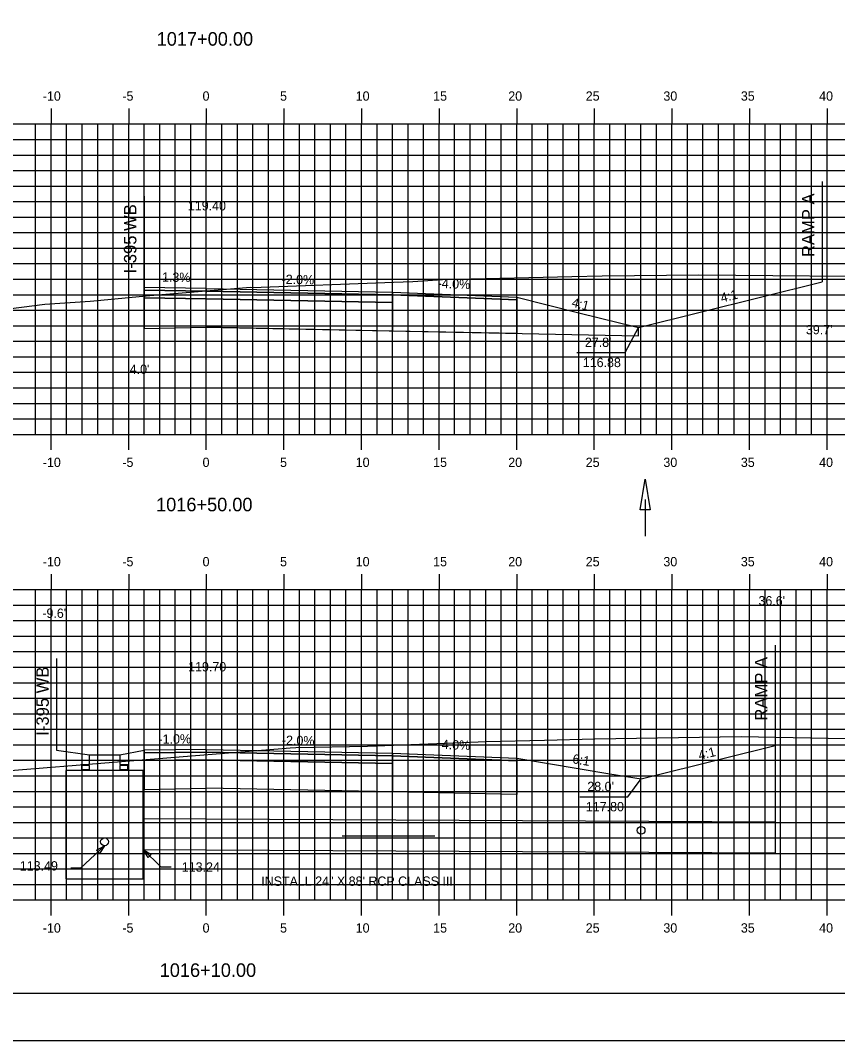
# Model space of a CAD drawing. Extents: x 853291 to 853462, y 365624 to 365734.
# Drawn here: x 853361.8 to 853414.5, y 365624 to 365689.7 of the extents above; entities that cross this region are included whole.
import ezdxf

# ---------------------------------------------------------------- set-up
doc = ezdxf.new("R2010")
doc.units = 0
for name, color, linetype in [('ANNOTATION', 7, 'Continuous'), ('BORDER', 7, 'Continuous'), ('D_Drainage_CB_TypeA1-B1', 7, 'Continuous'), ('D_Drainage_Culvert', 7, 'Continuous'), ('D_Drainage_Ditch_Line', 7, 'Continuous'), ('D_Drainage_Text', 7, 'Continuous'), ('D_Roadway_Centerline', 7, 'Continuous'), ('D_Roadway_Centerline_Text', 7, 'Continuous'), ('D_Roadway_Edge_Shoulder', 7, 'Continuous'), ('D_Roadway_Edge_TW', 7, 'Continuous'), ('D_Roadway_FinishedGrade', 7, 'Continuous'), ('D_Roadway_Pavement', 7, 'Continuous'), ('D_Roadway_SubGrade', 7, 'Continuous'), ('D_Text_Standard', 7, 'Continuous'), ('Default', 7, 'Continuous'), ('H_V ANNOTATION', 7, 'Continuous'), ('M_Roadway_Centerline', 7, 'Continuous'), ('MAJOR', 7, 'Continuous'), ('MINOR', 7, 'Continuous'), ('PLOT BOUNDARY', 7, 'Continuous'), ('S_Roadway_Centerline', 7, 'Continuous')]:
    doc.layers.add(name, color=color, linetype=linetype)

msp = doc.modelspace()

# ---------------------------------------------------------------- linework, layer by layer
at = {"layer": 'ANNOTATION'}
msp.add_line((853410.467, 365642.983), (853410.467, 365636.07), dxfattribs=at)
for points in [[(853397.691, 365668.298), (853400.801, 365668.298), (853401.666, 365669.903)], [(853397.875, 365639.678), (853400.985, 365639.678), (853401.839, 365640.83)]]:
    msp.add_lwpolyline(points, dxfattribs=at)
at = {"layer": 'BORDER'}
msp.add_lwpolyline([(853298.818, 365627.027), (853458.818, 365627.027), (853458.818, 365732.027), (853298.818, 365732.027)], close=True, dxfattribs=at)
at = {"layer": 'D_Drainage_CB_TypeA1-B1'}
msp.add_lwpolyline([(853365.758, 365641.753), (853366.283, 365641.753), (853366.283, 365642.377), (853368.252, 365642.377), (853368.252, 365641.753), (853368.777, 365641.753)], dxfattribs=at)
for points in [[(853364.774, 365634.386), (853369.757, 365634.386), (853369.757, 365641.372), (853364.774, 365641.372)], [(853365.783, 365641.69), (853365.783, 365641.44), (853366.283, 365641.44), (853366.283, 365641.69)], [(853368.252, 365641.69), (853368.252, 365641.44), (853368.752, 365641.44), (853368.752, 365641.69)]]:
    msp.add_lwpolyline(points, close=True, dxfattribs=at)
at = {"layer": 'D_Drainage_Culvert'}
for p, q in [((853369.757, 365638.273), (853410.467, 365638.07)), ((853382.565, 365637.171), (853388.534, 365637.171)), ((853369.757, 365636.273), (853410.467, 365636.07))]:
    msp.add_line(p, q, dxfattribs=at)
for centre in [(853401.832, 365637.514), (853367.261, 365636.776)]:
    msp.add_circle(centre, 0.25, dxfattribs=at)
at = {"layer": 'D_Drainage_Ditch_Line'}
msp.add_line((853402.091, 365658.824), (853402.091, 365656.474), dxfattribs=at)
msp.add_lwpolyline([(853402.419, 365658.167), (853401.763, 365658.167), (853402.091, 365660.136)], close=True, dxfattribs=at)
at = {"layer": 'D_Roadway_Centerline'}
for p, q in [((853364.175, 365642.691), (853366.283, 365642.377)), ((853368.252, 365642.377), (853369.817, 365642.682)), ((853410.467, 365642.983), (853410.467, 365640.483))]:
    msp.add_line(p, q, dxfattribs=at)
for points in [[(853401.666, 365669.903), (853405.544, 365670.869), (853413.506, 365672.851)], [(853393.818, 365671.865), (853397.818, 365670.865), (853401.666, 365669.903)], [(853401.839, 365640.83), (853407.088, 365642.14), (853410.467, 365642.983)], [(853393.822, 365642.166), (853399.822, 365641.166), (853401.839, 365640.83)]]:
    msp.add_lwpolyline(points, dxfattribs=at)
at = {"layer": 'D_Roadway_Edge_Shoulder'}
for points in [[(853373.818, 365672.425), (853369.818, 365672.481), (853369.818, 365672.314), (853373.818, 365672.258)], [(853385.818, 365672.185), (853393.818, 365671.865), (853393.818, 365671.698), (853385.818, 365672.018)], [(853373.818, 365642.723), (853369.817, 365642.682), (853369.817, 365642.516), (853373.818, 365642.557)], [(853385.821, 365642.485), (853393.822, 365642.166), (853393.822, 365642), (853385.821, 365642.319)]]:
    msp.add_lwpolyline(points, close=True, dxfattribs=at)
at = {"layer": 'D_Roadway_Edge_TW'}
for points in [[(853373.818, 365672.425), (853385.818, 365672.185), (853385.818, 365672.018), (853373.818, 365672.258)], [(853373.818, 365642.723), (853385.821, 365642.485), (853385.821, 365642.319), (853373.818, 365642.557)]]:
    msp.add_lwpolyline(points, close=True, dxfattribs=at)
for points in [[(853385.818, 365672.185), (853385.818, 365672.018)], [(853385.821, 365642.485), (853385.821, 365642.319)]]:
    msp.add_lwpolyline(points, dxfattribs=at)
at = {"layer": 'D_Roadway_FinishedGrade'}
for p, q in [((853369.818, 365672.481), (853369.818, 365672.231)), ((853373.818, 365672.425), (853373.818, 365672.175)), ((853385.818, 365672.185), (853385.818, 365671.935)), ((853393.818, 365671.865), (853393.818, 365671.615)), ((853369.817, 365642.682), (853369.817, 365642.432)), ((853373.818, 365642.723), (853373.818, 365642.473)), ((853385.821, 365642.485), (853385.821, 365642.235)), ((853393.822, 365642.166), (853393.822, 365641.916))]:
    msp.add_line(p, q, dxfattribs=at)
at = {"layer": 'D_Roadway_Pavement'}
for points in [[(853373.818, 365672.258), (853369.818, 365672.314), (853369.818, 365671.814), (853373.818, 365671.758)], [(853373.818, 365672.258), (853385.818, 365672.018), (853385.818, 365671.518), (853373.818, 365671.758)], [(853373.818, 365642.557), (853369.817, 365642.516), (853369.817, 365642.016), (853373.818, 365642.057)], [(853373.818, 365642.557), (853385.821, 365642.319), (853385.821, 365641.819), (853373.818, 365642.057)]]:
    msp.add_lwpolyline(points, close=True, dxfattribs=at)
for points in [[(853385.818, 365672.018), (853385.818, 365671.518)], [(853385.818, 365672.018), (853385.818, 365671.518)], [(853385.821, 365642.319), (853385.821, 365641.819)], [(853385.821, 365642.319), (853385.821, 365641.819)]]:
    msp.add_lwpolyline(points, dxfattribs=at)
at = {"layer": 'D_Roadway_SubGrade'}
for p, q in [((853413.506, 365679.312), (853413.506, 365672.851)), ((853369.818, 365678.385), (853369.818, 365669.845)), ((853410.467, 365649.445), (853410.467, 365636.07)), ((853364.175, 365648.595), (853364.175, 365642.691))]:
    msp.add_line(p, q, dxfattribs=at)
for points in [[(853373.818, 365671.758), (853369.818, 365671.814), (853369.818, 365672.314), (853369.818, 365672.481), (853369.818, 365669.845), (853373.818, 365669.925)], [(853373.818, 365671.758), (853385.818, 365671.518), (853385.818, 365669.685), (853373.818, 365669.925)], [(853385.818, 365671.518), (853385.818, 365672.018), (853393.818, 365671.698), (853393.818, 365671.865), (853393.818, 365669.525), (853385.818, 365669.685)], [(853373.818, 365642.057), (853369.817, 365642.016), (853369.817, 365642.516), (853369.817, 365642.682), (853369.817, 365640.142), (853373.818, 365640.223)], [(853373.818, 365642.057), (853385.821, 365641.819), (853385.821, 365639.985), (853373.818, 365640.223)], [(853385.821, 365641.819), (853385.821, 365642.319), (853393.822, 365642), (853393.822, 365642.166), (853393.822, 365639.826), (853385.821, 365639.985)]]:
    msp.add_lwpolyline(points, close=True, dxfattribs=at)
for points in [[(853385.818, 365671.518), (853385.818, 365669.685)], [(853373.818, 365669.925), (853401.655, 365669.368), (853401.666, 365669.903)], [(853385.821, 365641.819), (853385.821, 365639.985)]]:
    msp.add_lwpolyline(points, dxfattribs=at)
at = {"layer": 'D_Text_Standard'}
for points in [[(853367.261, 365636.526), (853365.715, 365635.084), (853365.095, 365635.084)], [(853369.757, 365636.273), (853370.879, 365635.153), (853371.559, 365635.153)]]:
    msp.add_lwpolyline(points, dxfattribs=at)
for points in [[(853367.261, 365636.526), (853366.94, 365636.019), (853366.739, 365636.23)], [(853369.757, 365636.273), (853370.272, 365635.965), (853370.066, 365635.759)]]:
    msp.add_lwpolyline(points, close=True, dxfattribs=at)
at = {"layer": 'Default'}
msp.add_lwpolyline([(853393.818, 365671.865), (853397.818, 365670.865), (853401.666, 365669.903)], dxfattribs=at)
at = {"layer": 'MAJOR'}
for p, q in [((853363.818, 365684.029), (853363.818, 365683.027)), ((853368.818, 365684.029), (853368.818, 365683.027)), ((853373.818, 365684.029), (853373.818, 365683.027)), ((853378.818, 365684.029), (853378.818, 365683.027)), ((853383.818, 365684.029), (853383.818, 365683.027)), ((853388.818, 365684.029), (853388.818, 365683.027)), ((853393.818, 365684.029), (853393.818, 365683.027)), ((853398.818, 365684.029), (853398.818, 365683.027)), ((853403.818, 365684.029), (853403.818, 365683.027)), ((853408.818, 365684.029), (853408.818, 365683.027)), ((853413.818, 365684.029), (853413.818, 365683.027)), ((853303.818, 365683.027), (853443.818, 365683.027)), ((853303.818, 365683.027), (853443.818, 365683.027)), ((853363.818, 365663.027), (853363.818, 365683.027)), ((853368.818, 365663.027), (853368.818, 365683.027)), ((853373.818, 365663.027), (853373.818, 365683.027)), ((853378.818, 365663.027), (853378.818, 365683.027)), ((853383.818, 365663.027), (853383.818, 365683.027)), ((853388.818, 365663.027), (853388.818, 365683.027)), ((853393.818, 365663.027), (853393.818, 365683.027)), ((853398.818, 365663.027), (853398.818, 365683.027)), ((853403.818, 365663.027), (853403.818, 365683.027)), ((853408.818, 365663.027), (853408.818, 365683.027)), ((853413.818, 365663.027), (853413.818, 365683.027)), ((853303.818, 365678.027), (853443.818, 365678.027)), ((853303.818, 365673.027), (853443.818, 365673.027)), ((853303.818, 365668.027), (853443.818, 365668.027)), ((853303.818, 365663.027), (853443.818, 365663.027)), ((853303.818, 365663.027), (853443.818, 365663.027)), ((853363.818, 365662.025), (853363.818, 365663.027)), ((853368.818, 365662.025), (853368.818, 365663.027)), ((853373.818, 365662.025), (853373.818, 365663.027)), ((853378.818, 365662.025), (853378.818, 365663.027)), ((853383.818, 365662.025), (853383.818, 365663.027)), ((853388.818, 365662.025), (853388.818, 365663.027)), ((853393.818, 365662.025), (853393.818, 365663.027)), ((853398.818, 365662.025), (853398.818, 365663.027)), ((853403.818, 365662.025), (853403.818, 365663.027)), ((853408.818, 365662.025), (853408.818, 365663.027)), ((853413.818, 365662.025), (853413.818, 365663.027)), ((853363.818, 365654.029), (853363.818, 365653.027)), ((853368.818, 365654.029), (853368.818, 365653.027)), ((853373.818, 365654.029), (853373.818, 365653.027)), ((853378.818, 365654.029), (853378.818, 365653.027)), ((853383.818, 365654.029), (853383.818, 365653.027)), ((853388.818, 365654.029), (853388.818, 365653.027)), ((853393.818, 365654.029), (853393.818, 365653.027)), ((853398.818, 365654.029), (853398.818, 365653.027)), ((853403.818, 365654.029), (853403.818, 365653.027)), ((853408.818, 365654.029), (853408.818, 365653.027)), ((853413.818, 365654.029), (853413.818, 365653.027)), ((853303.818, 365653.027), (853443.818, 365653.027)), ((853303.818, 365653.027), (853443.818, 365653.027)), ((853363.818, 365633.027), (853363.818, 365653.027)), ((853368.818, 365633.027), (853368.818, 365653.027)), ((853373.818, 365633.027), (853373.818, 365653.027)), ((853378.818, 365633.027), (853378.818, 365653.027)), ((853383.818, 365633.027), (853383.818, 365653.027)), ((853388.818, 365633.027), (853388.818, 365653.027)), ((853393.818, 365633.027), (853393.818, 365653.027)), ((853398.818, 365633.027), (853398.818, 365653.027)), ((853403.818, 365633.027), (853403.818, 365653.027)), ((853408.818, 365633.027), (853408.818, 365653.027)), ((853413.818, 365633.027), (853413.818, 365653.027)), ((853303.818, 365648.027), (853443.818, 365648.027)), ((853303.818, 365643.027), (853443.818, 365643.027)), ((853303.818, 365638.027), (853443.818, 365638.027)), ((853303.818, 365633.027), (853443.818, 365633.027)), ((853303.818, 365633.027), (853443.818, 365633.027)), ((853363.818, 365632.025), (853363.818, 365633.027)), ((853368.818, 365632.025), (853368.818, 365633.027)), ((853373.818, 365632.025), (853373.818, 365633.027)), ((853378.818, 365632.025), (853378.818, 365633.027)), ((853383.818, 365632.025), (853383.818, 365633.027)), ((853388.818, 365632.025), (853388.818, 365633.027)), ((853393.818, 365632.025), (853393.818, 365633.027)), ((853398.818, 365632.025), (853398.818, 365633.027)), ((853403.818, 365632.025), (853403.818, 365633.027)), ((853408.818, 365632.025), (853408.818, 365633.027)), ((853413.818, 365632.025), (853413.818, 365633.027))]:
    msp.add_line(p, q, dxfattribs=at)
at = {"layer": 'MINOR'}
for p, q in [((853362.818, 365663.027), (853362.818, 365683.027)), ((853364.818, 365663.027), (853364.818, 365683.027)), ((853365.818, 365663.027), (853365.818, 365683.027)), ((853366.818, 365663.027), (853366.818, 365683.027)), ((853367.818, 365663.027), (853367.818, 365683.027)), ((853369.818, 365663.027), (853369.818, 365683.027)), ((853370.818, 365663.027), (853370.818, 365683.027)), ((853371.818, 365663.027), (853371.818, 365683.027)), ((853372.818, 365663.027), (853372.818, 365683.027)), ((853374.818, 365663.027), (853374.818, 365683.027)), ((853375.818, 365663.027), (853375.818, 365683.027)), ((853376.818, 365663.027), (853376.818, 365683.027)), ((853377.818, 365663.027), (853377.818, 365683.027)), ((853379.818, 365663.027), (853379.818, 365683.027)), ((853380.818, 365663.027), (853380.818, 365683.027)), ((853381.818, 365663.027), (853381.818, 365683.027)), ((853382.818, 365663.027), (853382.818, 365683.027)), ((853384.818, 365663.027), (853384.818, 365683.027)), ((853385.818, 365663.027), (853385.818, 365683.027)), ((853386.818, 365663.027), (853386.818, 365683.027)), ((853387.818, 365663.027), (853387.818, 365683.027)), ((853389.818, 365663.027), (853389.818, 365683.027)), ((853390.818, 365663.027), (853390.818, 365683.027)), ((853391.818, 365663.027), (853391.818, 365683.027)), ((853392.818, 365663.027), (853392.818, 365683.027)), ((853394.818, 365663.027), (853394.818, 365683.027)), ((853395.818, 365663.027), (853395.818, 365683.027)), ((853396.818, 365663.027), (853396.818, 365683.027)), ((853397.818, 365663.027), (853397.818, 365683.027)), ((853399.818, 365663.027), (853399.818, 365683.027)), ((853400.818, 365663.027), (853400.818, 365683.027)), ((853401.818, 365663.027), (853401.818, 365683.027)), ((853402.818, 365663.027), (853402.818, 365683.027)), ((853404.818, 365663.027), (853404.818, 365683.027)), ((853405.818, 365663.027), (853405.818, 365683.027)), ((853406.818, 365663.027), (853406.818, 365683.027)), ((853407.818, 365663.027), (853407.818, 365683.027)), ((853409.818, 365663.027), (853409.818, 365683.027)), ((853410.818, 365663.027), (853410.818, 365683.027)), ((853411.818, 365663.027), (853411.818, 365683.027)), ((853412.818, 365663.027), (853412.818, 365683.027)), ((853303.818, 365682.027), (853443.818, 365682.027)), ((853303.818, 365681.027), (853443.818, 365681.027)), ((853303.818, 365680.027), (853443.818, 365680.027)), ((853303.818, 365679.027), (853443.818, 365679.027)), ((853303.818, 365677.027), (853443.818, 365677.027)), ((853303.818, 365676.027), (853443.818, 365676.027)), ((853303.818, 365675.027), (853443.818, 365675.027)), ((853303.818, 365674.027), (853443.818, 365674.027)), ((853303.818, 365672.027), (853443.818, 365672.027)), ((853303.818, 365671.027), (853443.818, 365671.027)), ((853303.818, 365670.027), (853443.818, 365670.027)), ((853303.818, 365669.027), (853443.818, 365669.027)), ((853303.818, 365667.027), (853443.818, 365667.027)), ((853303.818, 365666.027), (853443.818, 365666.027)), ((853303.818, 365665.027), (853443.818, 365665.027)), ((853303.818, 365664.027), (853443.818, 365664.027)), ((853362.818, 365633.027), (853362.818, 365653.027)), ((853364.818, 365633.027), (853364.818, 365653.027)), ((853365.818, 365633.027), (853365.818, 365653.027)), ((853366.818, 365633.027), (853366.818, 365653.027)), ((853367.818, 365633.027), (853367.818, 365653.027)), ((853369.818, 365633.027), (853369.818, 365653.027)), ((853370.818, 365633.027), (853370.818, 365653.027)), ((853371.818, 365633.027), (853371.818, 365653.027)), ((853372.818, 365633.027), (853372.818, 365653.027)), ((853374.818, 365633.027), (853374.818, 365653.027)), ((853375.818, 365633.027), (853375.818, 365653.027)), ((853376.818, 365633.027), (853376.818, 365653.027)), ((853377.818, 365633.027), (853377.818, 365653.027)), ((853379.818, 365633.027), (853379.818, 365653.027)), ((853380.818, 365633.027), (853380.818, 365653.027)), ((853381.818, 365633.027), (853381.818, 365653.027)), ((853382.818, 365633.027), (853382.818, 365653.027)), ((853384.818, 365633.027), (853384.818, 365653.027)), ((853385.818, 365633.027), (853385.818, 365653.027)), ((853386.818, 365633.027), (853386.818, 365653.027)), ((853387.818, 365633.027), (853387.818, 365653.027)), ((853389.818, 365633.027), (853389.818, 365653.027)), ((853390.818, 365633.027), (853390.818, 365653.027)), ((853391.818, 365633.027), (853391.818, 365653.027)), ((853392.818, 365633.027), (853392.818, 365653.027)), ((853394.818, 365633.027), (853394.818, 365653.027)), ((853395.818, 365633.027), (853395.818, 365653.027)), ((853396.818, 365633.027), (853396.818, 365653.027)), ((853397.818, 365633.027), (853397.818, 365653.027)), ((853399.818, 365633.027), (853399.818, 365653.027)), ((853400.818, 365633.027), (853400.818, 365653.027)), ((853401.818, 365633.027), (853401.818, 365653.027)), ((853402.818, 365633.027), (853402.818, 365653.027)), ((853404.818, 365633.027), (853404.818, 365653.027)), ((853405.818, 365633.027), (853405.818, 365653.027)), ((853406.818, 365633.027), (853406.818, 365653.027)), ((853407.818, 365633.027), (853407.818, 365653.027)), ((853409.818, 365633.027), (853409.818, 365653.027)), ((853410.818, 365633.027), (853410.818, 365653.027)), ((853411.818, 365633.027), (853411.818, 365653.027)), ((853412.818, 365633.027), (853412.818, 365653.027)), ((853303.818, 365652.027), (853443.818, 365652.027)), ((853303.818, 365651.027), (853443.818, 365651.027)), ((853303.818, 365650.027), (853443.818, 365650.027)), ((853303.818, 365649.027), (853443.818, 365649.027)), ((853303.818, 365647.027), (853443.818, 365647.027)), ((853303.818, 365646.027), (853443.818, 365646.027)), ((853303.818, 365645.027), (853443.818, 365645.027)), ((853303.818, 365644.027), (853443.818, 365644.027)), ((853303.818, 365642.027), (853443.818, 365642.027)), ((853303.818, 365641.027), (853443.818, 365641.027)), ((853303.818, 365640.027), (853443.818, 365640.027)), ((853303.818, 365639.027), (853443.818, 365639.027)), ((853303.818, 365637.027), (853443.818, 365637.027)), ((853303.818, 365636.027), (853443.818, 365636.027)), ((853303.818, 365635.027), (853443.818, 365635.027)), ((853303.818, 365634.027), (853443.818, 365634.027))]:
    msp.add_line(p, q, dxfattribs=at)
at = {"layer": 'PLOT BOUNDARY'}
msp.add_lwpolyline([(853290.725, 365623.968), (853460.725, 365623.968), (853460.725, 365733.968), (853290.725, 365733.968)], close=True, dxfattribs=at)
at = {"layer": 'S_Roadway_Centerline'}
for points in [[(853358.875, 365670.837), (853363.418, 365671.415), (853366.332, 365671.608), (853370.17, 365671.984), (853376.668, 365672.507), (853376.793, 365672.501), (853385.888, 365672.827), (853387.116, 365672.883), (853389.357, 365673.032), (853389.951, 365673.032), (853397.371, 365673.197), (853399.332, 365673.233), (853405.546, 365673.305), (853419.84, 365673.18), (853423.032, 365673.134), (853423.924, 365673.108), (853426.083, 365673.03), (853429.997, 365672.918), (853435.022, 365672.7), (853439.425, 365672.472), (853442.303, 365672.336), (853443.818, 365672.022)], [(853359.562, 365641.24), (853378.698, 365642.784), (853379.227, 365642.835), (853379.596, 365642.847), (853384.21, 365642.929), (853389.782, 365643.151), (853391.849, 365643.245), (853395.6, 365643.328), (853398.86, 365643.411), (853408.287, 365643.553), (853418.351, 365643.372), (853419.706, 365643.349), (853423.234, 365643.292), (853424.384, 365643.233), (853430.917, 365642.97), (853432.314, 365642.913), (853435.76, 365642.761), (853439.046, 365642.595), (853441.367, 365642.215), (853443.818, 365641.784)]]:
    msp.add_lwpolyline(points, dxfattribs=at)

# ---------------------------------------------------------------- texts
at = {"layer": 'ANNOTATION'}
for s, height, rotation, p in [('RAMP A', 0.8, 90, (853412.999, 365674.453)), ('I-395 WB', 0.8, 90, (853369.311, 365673.399)), ('1.3%', 0.6, 359.19792, (853370.961, 365672.865)), ('-2.0%', 0.6, 358.85423, (853378.663, 365672.728)), ('-4.0%', 0.6, 357.7093, (853388.715, 365672.47)), ('4:1', 0.6, 13.98162, (853407.032, 365671.514)), ('4:1', 0.6, 345.96376, (853397.317, 365671.265)), ("27.8' ", 0.6, 360, (853398.209, 365668.661)), ('116.88', 0.6, 360, (853398.075, 365667.361)), ('RAMP A', 0.8, 90, (853409.96, 365644.585)), ('I-395 WB', 0.8, 90, (853363.668, 365643.609)), ('-1.0%', 0.6, 0.579, (853370.74, 365643.092)), ('-2.0%', 0.6, 358.86451, (853378.684, 365643.027)), ('-4.0%', 0.6, 357.71985, (853388.717, 365642.77)), ('4:1', 0.6, 14.01143, (853405.599, 365642.043)), ('6:1', 0.6, 350.53768, (853397.377, 365641.844)), ("28.0' ", 0.6, 360, (853398.366, 365640.041)), ('117.80', 0.6, 360, (853398.272, 365638.741))]:
    msp.add_text(s, height=height, rotation=rotation, dxfattribs=at).set_placement(p)
at = {"layer": 'D_Drainage_Text'}
msp.add_text('INSTALL 24" X 88\' RCP CLASS III', height=0.6, dxfattribs=at).set_placement((853377.355, 365633.94))
at = {"layer": 'D_Roadway_Centerline'}
for s, p in [('C', (853373.813, 365672.425)), ('L', (853373.818, 365672.417))]:
    msp.add_text(s, height=0.0146, dxfattribs=at).set_placement(p)
at = {"layer": 'D_Roadway_Centerline_Text'}
for s, p in [('119.40', (853372.63, 365677.457)), ('119.70', (853372.646, 365647.755))]:
    msp.add_text(s, height=0.6, dxfattribs=at).set_placement(p)
at = {"layer": 'D_Text_Standard'}
for s, p in [("39.7'", (853412.449, 365669.476)), ("4.0'", (853368.884, 365666.926)), ("36.6'", (853409.394, 365652.009)), ("-9.6'", (853363.252, 365651.204)), ('113.49', (853361.801, 365634.927)), ('113.24', (853372.239, 365634.853))]:
    msp.add_text(s, height=0.6, dxfattribs=at).set_placement(p)
at = {"layer": 'H_V ANNOTATION'}
for s, height, p in [('1017+00.00', 0.875, (853370.619, 365688.07)), ('-10', 0.6, (853363.283, 365684.527)), ('-5', 0.6, (853368.409, 365684.527)), ('0', 0.6, (853373.577, 365684.527)), ('5', 0.6, (853378.569, 365684.527)), ('10', 0.6, (853383.443, 365684.527)), ('15', 0.6, (853388.435, 365684.527)), ('20', 0.6, (853393.272, 365684.527)), ('25', 0.6, (853398.264, 365684.527)), ('30', 0.6, (853403.267, 365684.527)), ('35', 0.6, (853408.259, 365684.527)), ('40', 0.6, (853413.304, 365684.527)), ('-10', 0.6, (853363.283, 365660.927)), ('-5', 0.6, (853368.409, 365660.927)), ('0', 0.6, (853373.577, 365660.927)), ('5', 0.6, (853378.569, 365660.927)), ('10', 0.6, (853383.443, 365660.927)), ('15', 0.6, (853388.435, 365660.927)), ('20', 0.6, (853393.272, 365660.927)), ('25', 0.6, (853398.264, 365660.927)), ('30', 0.6, (853403.267, 365660.927)), ('35', 0.6, (853408.259, 365660.927)), ('40', 0.6, (853413.304, 365660.927)), ('1016+50.00', 0.875, (853370.58, 365658.07)), ('-10', 0.6, (853363.283, 365654.527)), ('-5', 0.6, (853368.409, 365654.527)), ('0', 0.6, (853373.577, 365654.527)), ('5', 0.6, (853378.569, 365654.527)), ('10', 0.6, (853383.443, 365654.527)), ('15', 0.6, (853388.435, 365654.527)), ('20', 0.6, (853393.272, 365654.527)), ('25', 0.6, (853398.264, 365654.527)), ('30', 0.6, (853403.267, 365654.527)), ('35', 0.6, (853408.259, 365654.527)), ('40', 0.6, (853413.304, 365654.527)), ('-10', 0.6, (853363.283, 365630.927)), ('-5', 0.6, (853368.409, 365630.927)), ('0', 0.6, (853373.577, 365630.927)), ('5', 0.6, (853378.569, 365630.927)), ('10', 0.6, (853383.443, 365630.927)), ('15', 0.6, (853388.435, 365630.927)), ('20', 0.6, (853393.272, 365630.927)), ('25', 0.6, (853398.264, 365630.927)), ('30', 0.6, (853403.267, 365630.927)), ('35', 0.6, (853408.259, 365630.927)), ('40', 0.6, (853413.304, 365630.927)), ('1016+10.00', 0.875, (853370.814, 365628.07))]:
    msp.add_text(s, height=height, dxfattribs=at).set_placement(p)
at = {"layer": 'M_Roadway_Centerline'}
for s, p in [('C', (853389.352, 365673.032)), ('L', (853389.357, 365673.025))]:
    msp.add_text(s, height=0.0146, dxfattribs=at).set_placement(p)

doc.saveas('drawing.dxf')
